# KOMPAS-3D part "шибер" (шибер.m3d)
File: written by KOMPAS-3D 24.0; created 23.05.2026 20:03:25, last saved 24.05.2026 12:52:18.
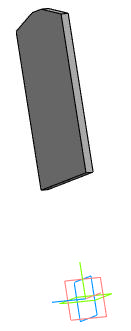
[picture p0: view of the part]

Document properties: Автор: R2D2; Полное имя файла: E:\Работа\Зайцев\GVKR1331E-1W-Fb-2P Задвижка шиберная DN.ru Ду50-300 Ру16-10-6\исходные материалы\DN150\шибер.m3d

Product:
- Part/product: шибер
    Масса: 2.222585
    Раздел спецификации: Прочие изделия
    Примечание: D040-08800

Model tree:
1. Эскиз:5  (with: Грань.Элемент выдавливания:1, Вершина.Элемент выдавливания:15)
2. Элемент выдавливания:6
     Расстояние 1 = 10

Referenced files in E:\Работа\Зайцев\GVKR1331E-1W-Fb-2P Задвижка шиберная DN.ru Ду50-300 Ру16-10-6\исходные материалы\DN150\: GVKR1331E-1W-Fb-2P Задвижка шиберная с выдвижным штоком DN.ru Ду150 Ру10.a3d
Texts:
  Затвор дисковый DN.ru Ду Ру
